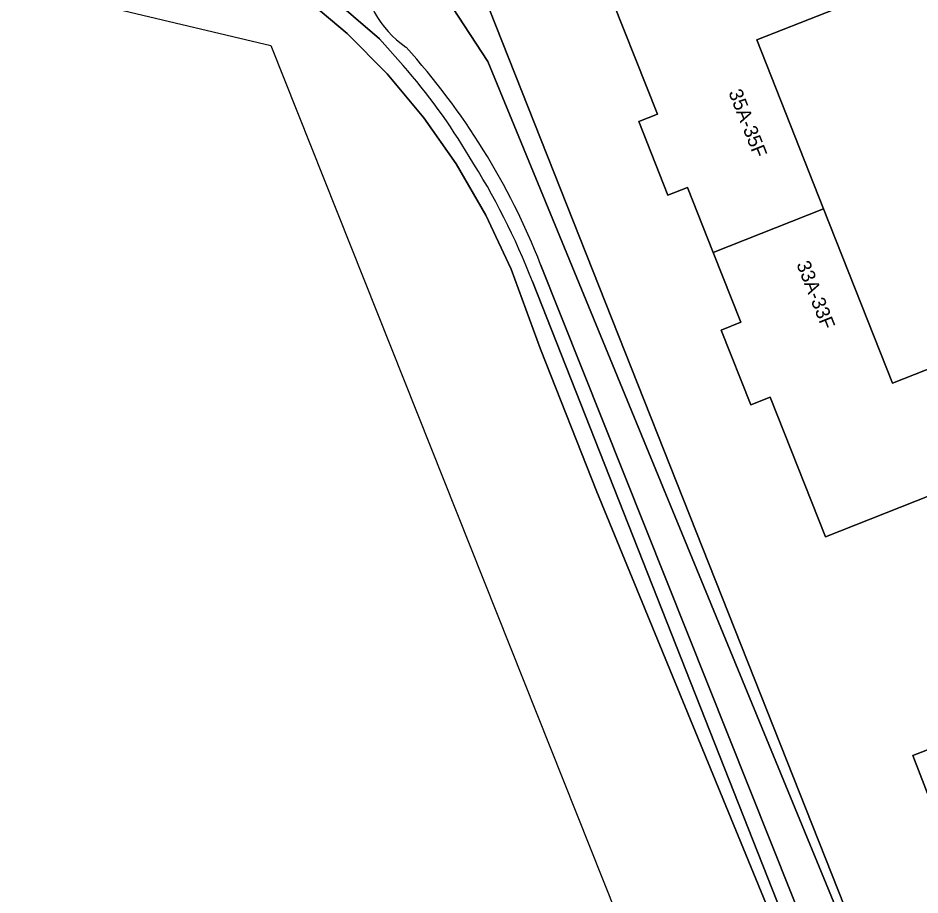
# Model space of a CAD drawing. Extents: x 158472 to 159562, y 388525 to 389606.
# Drawn here: x 158927 to 158991.6, y 388619.1 to 388681.9 of the extents above; entities that cross this region are included whole.
import ezdxf

# ---------------------------------------------------------------- set-up
doc = ezdxf.new("R2010")
doc.units = 0
for name, color, linetype in [('IMGEO_Erf', 7, 'Continuous'), ('IMGEO_Grasland_overig', 7, 'Continuous'), ('IMGEO_Groenvoorziening', 7, 'Continuous'), ('IMGEO_Hek', 7, 'Continuous'), ('IMGEO_Meer_plas_ven_vijver', 7, 'Continuous'), ('IMGEO_Oever', 7, 'Continuous'), ('IMGEO_Pand', 7, 'Continuous'), ('IMGEO_Pand_nummerreeks', 7, 'Continuous'), ('IMGEO_Voetpad_halfverhard', 7, 'Continuous'), ('IMGEO_Walbescherming', 7, 'Continuous')]:
    doc.layers.add(name, color=color, linetype=linetype)

msp = doc.modelspace()

# ---------------------------------------------------------------- linework, layer by layer
at = {"layer": 'IMGEO_Erf'}
msp.add_lwpolyline([(158993.829, 388682.38), (158996.134, 388683.253), (158991.931, 388694.055), (158986.773, 388692.12), (158989.883, 388684.264), (158979.9, 388680.312), (158984.692, 388668.208), (158989.637, 388655.719), (158999.634, 388659.677), (158998.352, 388662.753), (159000, 388663.406), (159001.095, 388663.839), (159000, 388666.634), (158997.541, 388672.907), (158996.538, 388675.467)], close=True, dxfattribs=at)
for points in [[(158957.964, 388689.565), (158991.293, 388605.352)], [(158992.361, 388647.705), (158984.816, 388644.718), (158980.856, 388654.72), (158979.486, 388654.177), (158977.364, 388659.536), (158978.764, 388660.091), (158976.789, 388665.079), (158974.938, 388669.754), (158973.545, 388669.202), (158971.458, 388674.473), (158972.794, 388675.002), (158968.815, 388685.052)], [(158994.969, 388618.982), (158991.07, 388629.056), (158998.51, 388631.936)]]:
    msp.add_lwpolyline(points, dxfattribs=at)
at = {"layer": 'IMGEO_Grasland_overig'}
msp.add_lwpolyline([(158991.293, 388605.352), (158957.964, 388689.565), (158956.571, 388688.996), (158955.214, 388688.441), (158955.178, 388688.038), (158955.022, 388686.321), (158956.851, 388684.593), (158960.645, 388678.761), (158990.911, 388605.19)], close=True, dxfattribs=at)
at = {"layer": 'IMGEO_Groenvoorziening'}
for points in [[(158960.645, 388678.761), (158956.851, 388684.593), (158955.022, 388686.321), (158955.178, 388688.038), (158953.025, 388689.6)], [(158964.429, 388664.228), (158988.389, 388604.118), (158990.911, 388605.19), (158960.645, 388678.761)]]:
    msp.add_lwpolyline(points, dxfattribs=at)
for centre, radius, start, end in [((158958.93, 388685.8), 7.298, 182.30646, 235.38979), ((158917.183, 388645.725), 50.74, 21.38713, 42.17718)]:
    msp.add_arc(centre, radius, start, end, dxfattribs=at)
at = {"layer": 'IMGEO_Hek'}
msp.add_lwpolyline([(158955.178, 388688.038), (158955.022, 388686.321), (158956.851, 388684.593), (158960.645, 388678.761), (158990.911, 388605.19)], dxfattribs=at)
at = {"layer": 'IMGEO_Meer_plas_ven_vijver'}
for points in [[(158980.947, 388617.566), (158968.458, 388647.949), (158964.408, 388658.159), (158962.318, 388663.898), (158960.512, 388667.76), (158958.368, 388671.444), (158956.052, 388674.731), (158953.445, 388677.881), (158950.566, 388680.786), (158947.44, 388683.422), (158946.319, 388684.258), (158946.034, 388684.462), (158942.359, 388686.96), (158939.152, 388688.776), (158936.537, 388689.763), (158933.78, 388690.674), (158930.531, 388691.605), (158890.03, 388700.878), (158870.659, 388705.032), (158857.904, 388707.552), (158827.937, 388714.025)], [(158822.445, 388708.992), (158897.018, 388691.315), (158945.096, 388679.918), (158977.475, 388598.587), (159006.711, 388525.15)]]:
    msp.add_lwpolyline(points, dxfattribs=at)
at = {"layer": 'IMGEO_Oever'}
for points in [[(158954.579, 388678.491), (158952.88, 388680.402), (158949.155, 388683.622), (158947.148, 388685.358), (158946.371, 388685.73), (158939.378, 388689.077), (158934.089, 388691.624), (158923.645, 388694.298), (158900.441, 388699.272), (158881.899, 388703.44), (158855.472, 388709), (158829.068, 388715.83), (158822.477, 388717.382), (158817.461, 388711.355), (158816.717, 388710.349), (158822.146, 388709.062)], [(158827.937, 388714.025), (158857.904, 388707.552), (158870.659, 388705.032), (158890.03, 388700.878), (158930.531, 388691.605), (158933.78, 388690.674), (158936.537, 388689.763), (158939.152, 388688.776), (158942.359, 388686.96), (158946.034, 388684.462), (158946.319, 388684.258), (158947.44, 388683.422), (158950.566, 388680.786), (158953.445, 388677.881), (158956.052, 388674.731), (158958.368, 388671.444), (158960.512, 388667.76), (158962.318, 388663.898), (158964.408, 388658.159), (158968.458, 388647.949), (158980.947, 388617.566), (158986.94, 388603.708), (158987.193, 388603.818), (158963.842, 388663.007)]]:
    msp.add_lwpolyline(points, dxfattribs=at)
for centre, radius, start, end in [((158920.651, 388648.887), 45.028, 30.8245, 41.10601), ((158915.503, 388644.2), 51.869, 21.25875, 32.35669)]:
    msp.add_arc(centre, radius, start, end, dxfattribs=at)
at = {"layer": 'IMGEO_Pand'}
for points in [[(158984.692, 388668.208), (158979.9, 388680.312), (158989.883, 388684.264), (158986.773, 388692.12), (158981.762, 388690.136), (158981.197, 388691.563), (158976.549, 388689.723), (158975.832, 388689.439), (158976.383, 388688.049), (158968.815, 388685.052), (158972.794, 388675.002), (158971.458, 388674.473), (158973.545, 388669.202), (158974.938, 388669.754), (158976.789, 388665.079)], [(159000, 388658.753), (158999.634, 388659.677), (158989.637, 388655.719), (158984.692, 388668.208), (158976.789, 388665.079), (158978.764, 388660.091), (158977.364, 388659.536), (158979.486, 388654.177), (158980.856, 388654.72), (158984.816, 388644.718), (158992.361, 388647.705), (158992.909, 388646.32), (158993.596, 388646.592), (158998.245, 388648.432), (158997.718, 388649.764), (159000, 388650.668), (159002.68, 388651.728), (159002.767, 388651.763)], [(159006.906, 388611.691), (159002.047, 388624.245), (159011.969, 388628.086), (159008.885, 388636.053), (159003.831, 388634.097), (159003.305, 388635.455), (159000, 388634.176), (158998.643, 388633.65), (158997.95, 388633.382), (158998.51, 388631.936), (158991.07, 388629.056), (158994.969, 388618.982), (158993.663, 388618.477), (158995.686, 388613.249), (158997.043, 388613.774), (158999.029, 388608.643), (159000, 388609.019), (159002.243, 388609.887)]]:
    msp.add_lwpolyline(points, close=True, dxfattribs=at)
at = {"layer": 'IMGEO_Voetpad_halfverhard'}
for points in [[(158951.854, 388687.699), (158949.155, 388683.622), (158952.88, 388680.402), (158954.579, 388678.491)], [(158990.46, 388598.969), (158989.761, 388600.676), (158988.389, 388604.118), (158964.429, 388664.228)], [(158963.842, 388663.007), (158987.193, 388603.818), (158986.94, 388603.708), (158990.839, 388594.444), (158991.75, 388592.186), (159012.538, 388540.636), (159013.987, 388537.691), (159015.664, 388535.517), (159017.294, 388533.727), (159019.351, 388532.038), (159020.362, 388532.463), (159019.242, 388533.931), (159017.045, 388535.834), (159015.143, 388538.144), (159013.648, 388541.179), (158993.589, 388590.993), (158991.982, 388594.983), (158990.46, 388598.969)]]:
    msp.add_lwpolyline(points, dxfattribs=at)
for centre, radius, start, end in [((158958.93, 388685.8), 7.298, 182.30646, 235.38979), ((158917.183, 388645.725), 50.74, 21.38713, 42.17718), ((158920.651, 388648.887), 45.028, 30.8245, 41.10601), ((158915.503, 388644.2), 51.869, 21.25875, 32.35669)]:
    msp.add_arc(centre, radius, start, end, dxfattribs=at)
at = {"layer": 'IMGEO_Walbescherming'}
msp.add_lwpolyline([(158968.458, 388647.949), (158964.408, 388658.159)], dxfattribs=at)

# ---------------------------------------------------------------- texts
at = {"layer": 'IMGEO_Pand_nummerreeks'}
for s, rotation, p in [('35A-35F', 291.59872, (158977.861, 388676.553)), ('33A-33F', 291.6003, (158982.729, 388664.256))]:
    msp.add_text(s, height=1, rotation=rotation, dxfattribs=at).set_placement(p)

doc.saveas('drawing.dxf')
